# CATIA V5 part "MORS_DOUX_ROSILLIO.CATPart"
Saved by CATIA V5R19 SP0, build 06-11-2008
Part number: MORS
Bounding box of the stored display mesh (mm): x 0 to 80, y -18 to 18, z 0 to 45
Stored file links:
  C:\Users\Laurent\Desktop\Sujet Bac national\Sujet National E33\CFAO Catia\MANDRIN_TBI-2\MORS_DOUX_ROSILLIO.CATPart
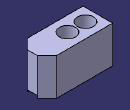
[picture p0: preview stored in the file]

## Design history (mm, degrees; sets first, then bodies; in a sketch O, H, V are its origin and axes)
Body1 (main body)
  Sketch1 on xy-plane, origin (0, 0, 0), H (1, 0, 0), V (0, 1, 0)
    line L1 (80, -18) -> (80, 18)
    line L2 (80, 18) -> (0, 18)
    line L3 (0, 18) -> (0, -18)
    line L4 (0, -18) -> (80, -18)
    distance L2 H = 18
    horizontal: L2 H, L4 H
    vertical: L1 V, L3 V
  Pad1: profile Sketch1, direction (0, 0, 1), length 45
  Chamfer1: length 12, angle 45, on edge [face of Pad1 from Sketch1.L1 | face of Pad1 from Sketch1.L4]; edge [face of Pad1 from Sketch1.L2 | face of Pad1 from Sketch1.L1]
  Sketch2 on end face of Pad1, origin (0, 0, 45), H (1, 0, 0), V (0, 1, 0)
    circle A1 centre (90, 0) radius 60
    point P1 (90, 0)
    circle A2 centre (90, 0) radius 100.0798
    distance P1 V = 90
    radius A1 = 60
    coincidence: P1 H
  Pocket1: profile Sketch2, direction (0, 0, -1), length 20, deactivated
  Sketch3 on end face of Pad1, origin (0, 0, 45), H (1, 0, 0), V (0, 1, 0)
    circle A1 centre (90, 0) radius 35
    point P1 (90, 0)
    circle A2 centre (90, 0) radius 67.1404
    radius A1 = 35
    distance P1 V = 90
    coincidence: P1 H
  Pocket2: profile Sketch3, direction (0, 0, -1), length 10, deactivated
  Sketch4 on end face of Pad1, origin (59, 0, 45), H (1, 0, 0), V (0, 1, 0)
    point P1 (0, 0)
    reference projected point E1 (0, 0) from Sketch8.P1
    coincidence: E1 P1
  Hole1: placed by Sketch4, at (59, 0, 45) direction (0, 0, -1), diameter 10, through (limit type 3), counterbore diameter 20, counterbore depth 30, deactivated
  Sketch5 on end face of Pad1, origin (37, 0, 45), H (1, 0, 0), V (0, 1, 0)
    point P1 (0, 0)
    reference projected point E1 (0, 0) from Sketch8.P2
    coincidence: E1 P1
  Hole2: placed by Sketch5, at (37, 0, 45) direction (0, 0, -1), diameter 10, through (limit type 3), counterbore diameter 20, counterbore depth 30
  Sketch6 on end face of Pad1, origin (15, 0, 45), H (1, 0, 0), V (0, 1, 0)
    point P1 (0, 0)
    reference projected point E1 (0, 0) from Sketch8.P3
    coincidence: E1 P1
  Hole3: placed by Sketch6, at (15, 0, 45) direction (0, 0, -1), diameter 10, through (limit type 3), counterbore diameter 20, counterbore depth 30
  Sketch7 on start face of Pad1, origin (0, 0, 0), H (1, 0, 0), V (0, -1, 0)
    line L1 (-10.0018, 6.5) -> (90.782, 6.5)
    line L2 (90.782, 6.5) -> (90.782, -6.5)
    line L3 (90.782, -6.5) -> (-10.0018, -6.5)
    line L4 (-10.0018, -6.5) -> (-10.0018, 6.5)
    distance L1 H = 6.5
    length L4 = 13
    horizontal: L1 H, L3 H
    vertical: L2 V, L4 V
  Pocket3: profile Sketch7, direction (0, 0, 1), length 3
  Sketch8 on end face of Pad1, origin (0, 0, 45), H (1, 0, 0), V (0, 1, 0)
    point P1 (59, 0)
    point P2 (37, 0)
    point P3 (15, 0)
    distance P1 P2 = 22
    distance P2 P3 = 22
    distance P3 V = 15
    coincidence: P1 H, P2 H, P3 H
